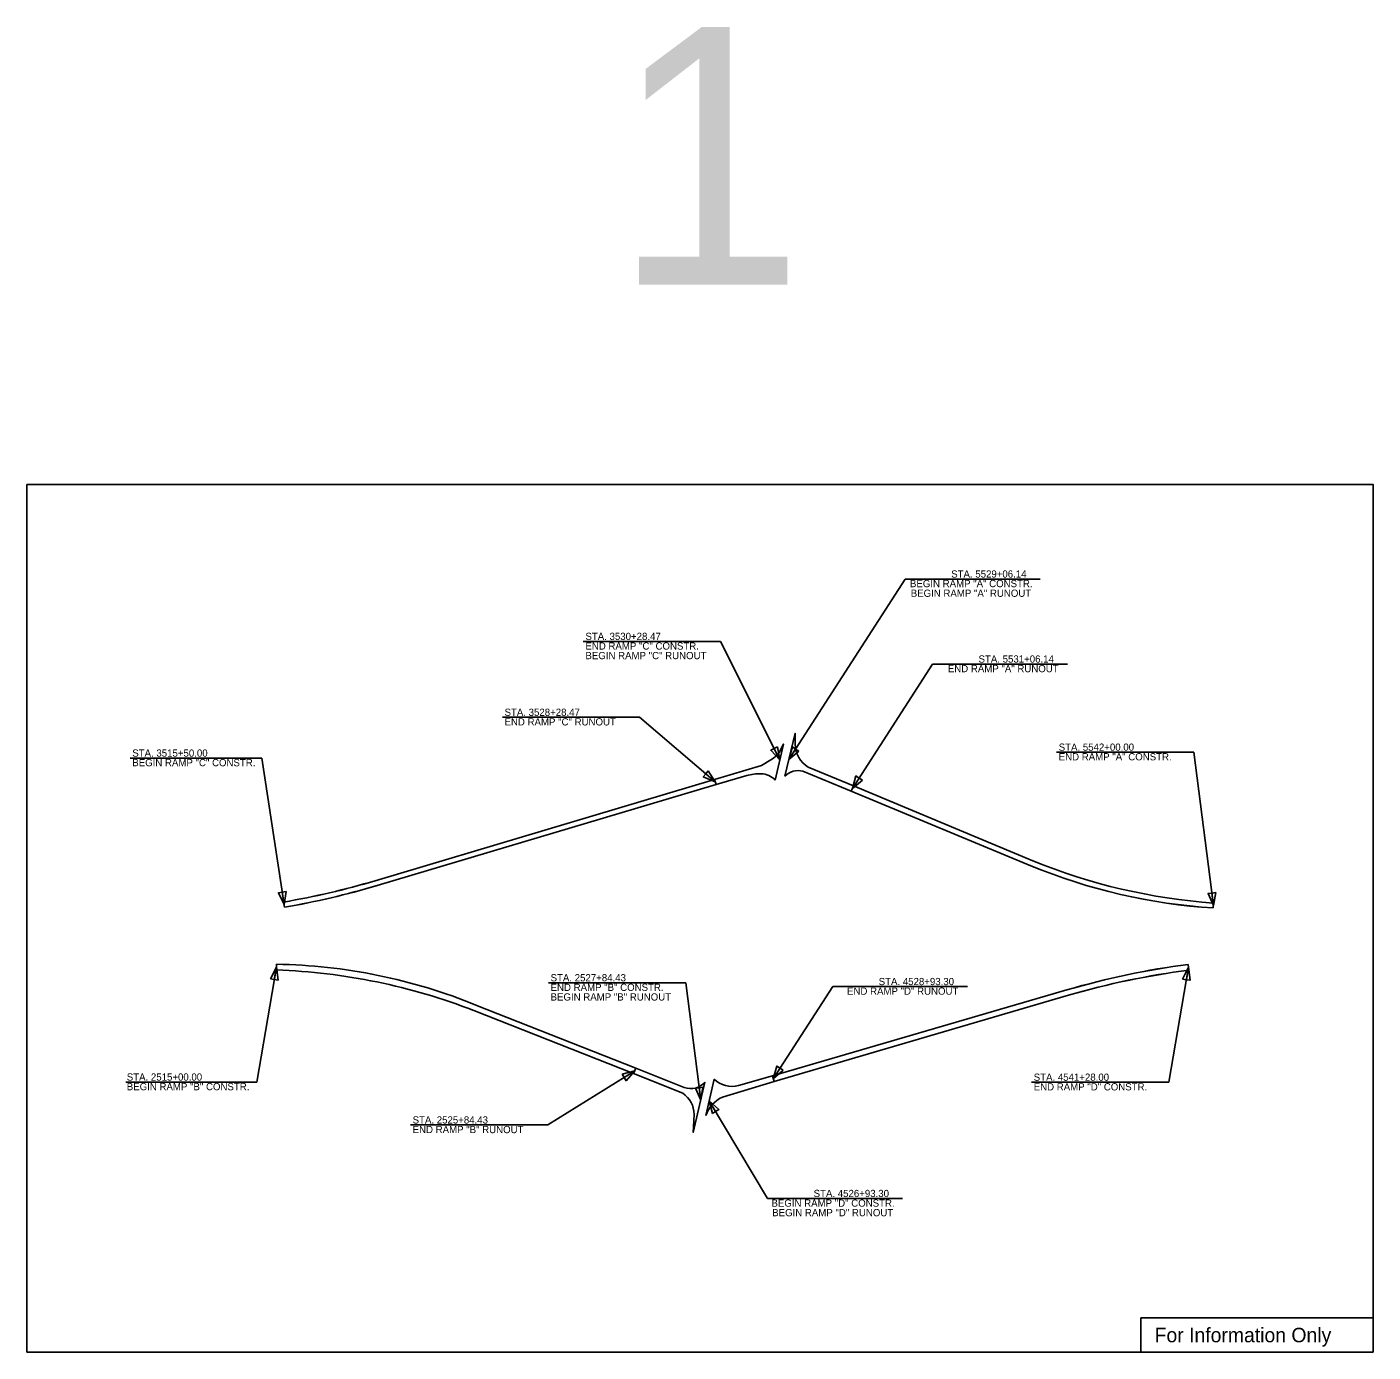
# Model space of a CAD drawing. Extents: x 10133 to 81668, y 7924 to 11018.
# Drawn here: x 10133 to 13268, y 7924 to 11009 of the extents above; entities that cross this region are included whole.
import ezdxf

# ---------------------------------------------------------------- set-up
doc = ezdxf.new("R2010")
doc.units = 0
for name, color, linetype in [('Shape', 7, 'Continuous'), ('SheetBorder', 7, 'Continuous'), ('SheetText', 7, 'Continuous'), ('Text', 7, 'Continuous')]:
    doc.layers.add(name, color=color, linetype=linetype)

msp = doc.modelspace()

# ---------------------------------------------------------------- linework, layer by layer
at = {"layer": 'Shape'}
for p, q in [((11921.6, 9364.6), (11897.7, 9264.7)), ((11921.6, 9339.4), (11921.6, 9364.6)), ((11894.2, 9339.4), (11875, 9255.8)), ((11888.4, 9327.5), (11894.2, 9339.4)), ((11843.2, 9290), (11733.7, 9257.4)), ((11864.8, 9302.7), (11843.2, 9290)), ((11952.2, 9285.9), (12057.3, 9242.1)), ((11733.7, 9257.4), (10943.2, 9021.3)), ((11733.7, 9257.4), (11737.4, 9245.1)), ((11737.4, 9245.1), (11808.8, 9266.4)), ((12052.2, 9229.7), (11939.7, 9276.2)), ((11737.4, 9245.1), (10947.9, 9010.1)), ((12057.3, 9242.1), (12052.2, 9229.7)), ((12470.6, 9056.3), (12052.2, 9229.7)), ((12057.3, 9242.1), (12475.4, 9067.8)), ((10732.6, 8959.7), (10730.4, 8971.8)), ((10732.6, 8959.7), (10730.4, 8971.8)), ((12896.2, 8969.5), (12895.4, 8958)), ((12896.2, 8969.5), (12895.4, 8958)), ((10713.6, 8813.7), (10713.6, 8826.9)), ((10713.6, 8813.7), (10713.6, 8826.9)), ((12836.8, 8826.7), (12838.5, 8813.1)), ((12836.8, 8826.7), (12838.5, 8813.1)), ((12554.6, 8767.3), (11868.6, 8566.9)), ((11872.6, 8553.9), (12558.3, 8754.7)), ((11545.5, 8572.3), (11173.4, 8719.2)), ((11178.3, 8731.7), (11550.6, 8585.2)), ((11545.5, 8572.3), (11550.6, 8585.2)), ((11659.9, 8526.5), (11545.5, 8572.3)), ((11663.5, 8540.3), (11550.6, 8585.2)), ((11733.1, 8559.2), (11713.5, 8474.8)), ((11713.5, 8474.8), (11733.1, 8559.2)), ((11789.9, 8544.3), (11868.6, 8566.9)), ((11872.6, 8553.9), (11868.6, 8566.9)), ((11684.4, 8435.4), (11711.5, 8552.4)), ((11752.4, 8517.7), (11872.6, 8553.9)), ((11686.6, 8477.2), (11684.4, 8435.4)), ((11684.4, 8435.4), (11684.4, 8435.4))]:
    msp.add_line(p, q, dxfattribs=at)
for points in [[(11897.7, 9264.7), (11921.6, 9364.6), (11921.6, 9339.4)], [(11888.4, 9327.5), (11894.2, 9339.4), (11875, 9255.8)], [(11808.8, 9266.4), (11737.4, 9245.1), (11733.7, 9257.4), (11843.2, 9290), (11864.8, 9302.7)], [(11952.2, 9285.9), (12057.3, 9242.1), (12052.2, 9229.7), (11939.7, 9276.2)], [(10943.2, 9021.3), (11733.7, 9257.4), (11737.4, 9245.1), (10947.9, 9010.1)], [(12470.6, 9056.3), (12052.2, 9229.7), (12057.3, 9242.1), (12475.4, 9067.8)], [(12558.3, 8754.7), (11872.6, 8553.9), (11868.6, 8566.9), (12554.6, 8767.3)], [(11178.3, 8731.7), (11550.6, 8585.2), (11545.5, 8572.3), (11173.4, 8719.2)], [(11659.9, 8526.5), (11545.5, 8572.3), (11550.6, 8585.2), (11663.5, 8540.3)], [(11789.9, 8544.3), (11868.6, 8566.9), (11872.6, 8553.9), (11752.4, 8517.7)], [(11711.5, 8552.4), (11684.4, 8435.4), (11686.6, 8477.2)]]:
    msp.add_lwpolyline(points, dxfattribs=at)
for centre, radius, start, end in [((11838.2, 9351.6), 55.7, 298.4981, 334.3013), ((11838.3, 9351.6), 55.6, 298.484, 334.3154), ((11983.6, 9339.4), 62, 180, 239.622), ((11983.6, 9339.4), 62, 180, 239.622), ((11839.3, 9151.4), 119, 88.5446, 104.8592), ((11839.3, 9151.4), 119, 88.5446, 104.8592), ((11842.3, 9226.5), 43.8, 41.8893, 90), ((11842.3, 9226.5), 43.8, 41.8893, 90), ((11928.2, 9235.6), 42.2, 74.2791, 136.2465), ((11928.2, 9235.6), 42.2, 74.2791, 136.2465), ((12991.3, 10326.9), 1360.7, 247.7184, 265.9914), ((12991.3, 10326.9), 1360.7, 247.7184, 265.9914), ((12980.3, 10292.2), 1336.9, 247.5889, 266.3599), ((12977.1, 10278.3), 1322.8, 247.4883, 266.4605), ((10412.7, 10819.3), 1874.6, 279.7573, 286.4395), ((10435.3, 10722.1), 1775, 279.5696, 286.6272), ((10392, 10896), 1966.1, 279.9745, 286.4221), ((10412.4, 10809.2), 1877.1, 279.8215, 286.5751), ((10694, 7550), 1277.1, 67.7155, 89.1194), ((10694, 7550), 1277.1, 67.7155, 89.1194), ((10665.1, 7411.6), 1402.9, 68.7608, 88.018), ((10665.1, 7411.6), 1402.9, 68.7608, 88.018), ((13096, 6894.9), 1949.1, 97.644, 106.1275), ((13081.7, 6963), 1879.7, 97.4871, 106.2844), ((13075.4, 6972.2), 1856.1, 97.3336, 106.1779), ((13063.3, 7030.6), 1796.6, 97.1869, 106.3246), ((11774.9, 8603), 60.6, 226.3353, 284.343), ((11774.9, 8603), 60.6, 226.3353, 284.343), ((11679.4, 8578.8), 41.6, 247.5309, 320.656), ((11679.4, 8578.8), 41.6, 247.5309, 320.656), ((11624, 8475.1), 62.7, 1.9196, 55.0138), ((11624, 8475.1), 62.7, 1.9196, 55.0138), ((11784.5, 8449.6), 75.3, 115.2795, 160.4253), ((11784.5, 8449.6), 75.3, 115.2795, 160.4253)]:
    msp.add_arc(centre, radius, start, end, dxfattribs=at)
at = {"layer": 'SheetBorder'}
msp.add_lwpolyline([(10132.5, 9944), (13267.5, 9944), (13267.5, 7924), (10132.5, 7924)], close=True, dxfattribs=at)
at = {"layer": 'SheetText'}
msp.add_lwpolyline([(12727, 8003.4), (13267.5, 8003.4), (13267.5, 7924), (12727, 7924)], close=True, dxfattribs=at)
at = {"layer": 'Text'}
for p, q in [((11907, 9303.4), (12178.1, 9723.8)), ((12492.3, 9723.8), (12178.1, 9723.8)), ((11747.9, 9578.6), (11428.1, 9578.6)), ((11885.8, 9302.9), (11747.9, 9578.6)), ((12054.8, 9235.9), (12241.8, 9525.8)), ((12555.9, 9525.8), (12241.8, 9525.8)), ((11559.5, 9401.9), (11239.7, 9401.9)), ((11735.5, 9251.3), (11559.5, 9401.9)), ((12850.1, 9320.6), (12530.3, 9320.6)), ((12895.8, 8963.7), (12850.1, 9320.6)), ((10679.5, 9306.9), (10372.8, 9306.9)), ((10731.5, 8965.7), (10679.5, 9306.9)), ((10713.6, 8820.3), (10668, 8552.7)), ((12837.7, 8819.9), (12792, 8552.2)), ((11666.8, 8783.8), (11347, 8783.8)), ((11701.8, 8510.4), (11666.8, 8783.8)), ((11870.6, 8560.4), (12009, 8775)), ((12323.2, 8775), (12009, 8775)), ((11548, 8578.7), (11345.6, 8452.7)), ((10668, 8552.7), (10362.9, 8552.7)), ((12792, 8552.2), (12472.1, 8552.2)), ((11721.5, 8509.3), (11857.6, 8281.5)), ((11345.6, 8452.7), (11025.7, 8452.7)), ((12171.7, 8281.5), (11857.6, 8281.5))]:
    msp.add_line(p, q, dxfattribs=at)
for points in [[(11885.8, 9302.9), (11864.7, 9325.1), (11872.7, 9329.1)], [(11880.7, 9333.1), (11885.8, 9302.9), (11872.7, 9329.1)], [(11907, 9303.4), (11915.3, 9332.8), (11922.8, 9328)], [(11930.4, 9323.2), (11907, 9303.4), (11922.8, 9328)], [(11735.5, 9251.3), (11707.5, 9263.5), (11713.3, 9270.3)], [(11719.1, 9277.1), (11735.5, 9251.3), (11713.3, 9270.3)], [(12054.8, 9235.9), (12063.1, 9265.3), (12070.6, 9260.5)], [(12078.1, 9255.6), (12054.8, 9235.9), (12070.6, 9260.5)], [(10731.5, 8965.7), (10718.2, 8993.3), (10727.1, 8994.7)], [(10735.9, 8996), (10731.5, 8965.7), (10727.1, 8994.7)], [(12895.8, 8963.7), (12883.2, 8991.7), (12892.1, 8992.8)], [(12901, 8993.9), (12895.8, 8963.7), (12892.1, 8992.8)], [(10699.9, 8792.9), (10713.6, 8820.3), (10708.7, 8791.4)], [(10713.6, 8820.3), (10717.5, 8789.9), (10708.7, 8791.4)], [(12823.9, 8792.5), (12837.7, 8819.9), (12832.7, 8791)], [(12837.7, 8819.9), (12841.5, 8789.5), (12832.7, 8791)], [(11518.4, 8570.8), (11548, 8578.7), (11523.2, 8563.2)], [(11548, 8578.7), (11527.9, 8555.7), (11523.2, 8563.2)], [(11870.6, 8560.4), (11879, 8589.9), (11886.5, 8585)], [(11894, 8580.2), (11870.6, 8560.4), (11886.5, 8585)], [(11701.8, 8510.4), (11689.2, 8538.4), (11698.1, 8539.5)], [(11707, 8540.6), (11701.8, 8510.4), (11698.1, 8539.5)], [(11721.5, 8509.3), (11744.2, 8488.8), (11736.5, 8484.2)], [(11728.9, 8479.6), (11721.5, 8509.3), (11736.5, 8484.2)]]:
    msp.add_lwpolyline(points, close=True, dxfattribs=at)

# ---------------------------------------------------------------- texts
at = {"layer": 'SheetText'}
for s, height, p in [('1', 600, (11496.6, 10409.2)), ('For Information Only', 33.75, (12758.8, 7946.8))]:
    msp.add_text(s, height=height, dxfattribs=at).set_placement(p)
at = {"layer": 'Text'}
for s, p in [('BEGIN RAMP "A" CONSTR.', (12189, 9704.8)), ('STA. 5529+06.14', (12285, 9727.1)), ('BEGIN RAMP "A" RUNOUT', (12190.8, 9682.4)), ('STA. 3530+28.47', (11433.2, 9581.9)), ('END RAMP "C" CONSTR.', (11433.2, 9559.5)), ('BEGIN RAMP "C" RUNOUT', (11433.2, 9537.2)), ('STA. 5531+06.14', (12348.7, 9529.2)), ('END RAMP "A" RUNOUT', (12277.2, 9506.8)), ('STA. 3528+28.47', (11244.8, 9405.2)), ('END RAMP "C" RUNOUT', (11244.8, 9382.9)), ('STA. 3515+50.00', (10377.9, 9310.2)), ('STA. 5542+00.00', (12535.4, 9324)), ('END RAMP "A" CONSTR.', (12535.4, 9301.6)), ('BEGIN RAMP "C" CONSTR.', (10377.9, 9287.9)), ('STA. 2527+84.43', (11352.1, 8787.1)), ('END RAMP "B" CONSTR.', (11352.1, 8764.8)), ('STA. 4528+93.30', (12116.2, 8778.3)), ('BEGIN RAMP "B" RUNOUT', (11352.1, 8742.4)), ('END RAMP "D" RUNOUT', (12042.4, 8756)), ('STA. 2515+00.00', (10365.1, 8556)), ('STA. 4541+28.00', (12477.2, 8555.6)), ('BEGIN RAMP "B" CONSTR.', (10365.1, 8533.6)), ('END RAMP "D" CONSTR.', (12477.2, 8533.2)), ('STA. 2525+84.43', (11030.8, 8456.1)), ('END RAMP "B" RUNOUT', (11030.8, 8433.7)), ('BEGIN RAMP "D" CONSTR.', (11866.5, 8262.5)), ('STA. 4526+93.30', (11964.7, 8284.9)), ('BEGIN RAMP "D" RUNOUT', (11868.2, 8240.2))]:
    msp.add_text(s, height=16.8, dxfattribs=at).set_placement(p)

doc.saveas('drawing.dxf')
